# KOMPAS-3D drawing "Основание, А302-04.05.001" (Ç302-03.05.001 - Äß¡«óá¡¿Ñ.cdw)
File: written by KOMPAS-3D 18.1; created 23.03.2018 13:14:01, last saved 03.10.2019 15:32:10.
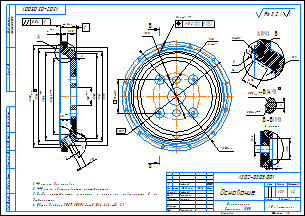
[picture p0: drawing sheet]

Sheet 1: A3, landscape

Document properties: Автор: Милов; Организация: Милов; Полное имя файла: D:\Мембранные насосы\Мембранный электропривод\А302-00.00.000 - ASTRA-302 (МЭ200)\Чертежи Полипропилен\А302-03.05.001 - Основание.cdw; Параметр неуказанной шероховатости: Ra 3,2; Масса: 1.33492

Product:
- Part/product: Основание  | designation А302-04.05.001
    Материал: Полипропилен  ГОСТ 26996-86 (density 900 kg/m3)
    Масса: 1.33492
    Раздел спецификации: Детали
    Форматы листов документа: A3
    source file: ..\Чертежи ПВХ\А302-02.05.001 - Основание.cdw, А302-03.05.001 - Основание.cdw
- Part/product: Основание  | designation А302-00.05.001
    Материал: Полипропилен  ГОСТ 26996-86 (density 900 kg/m3)
    Масса: 1.33086
    Раздел спецификации: Детали
    Форматы листов документа: A3
    source file: \\192.168.87.28\Konstructor_doc\Мембранные насосы\Мембранный электропривод\А302-00.00.000 - ASTRA-302 (МЭ200)\Чертежи\А302-00.05.001 - Основание.cdw
- Part/product: Основание  | designation А302-03.05.001
    Материал: Полипропилен  ГОСТ 26996-86 (density 900 kg/m3)
    Масса: 1.33086
    Раздел спецификации: Детали
    Форматы листов документа: A3

Title block, sheet 1: Наименование: Основание; designation: А302-03.05.001; Материал: Полипропилен / Стержень  300; Масса: 1,33; scale: 1:2; Количество листов документа: 1; organisation: АО «Астерион»; Форматы листов документа: A3; stored path: \\192.168.87.28\Konstructor_doc\Мембранные насосы\Мембранный электропривод\А302-00.00.000 - ASTRA-302 (МЭ200)\Чертежи\А302-00.05.001 - Основание.cdw; Разработал: Лифлянд; Проверил: Борисенко; Т. контр.: Лучихин; Утвердил: Григорьева

Views: Вид 1, Местный разрез 1, Вид:3, Проекционный вид 2, Выносной элемент 3, Разрез 4, Выносной элемент 5, Выносной элемент А, Выносной элемент, Разрез В-В, Выносной элемент Б
Referenced files in D:\Мембранные насосы\Мембранный электропривод\А302-00.00.000 - ASTRA-302 (МЭ200)\3Д\: А302-00.05.001 - Основание.m3d
Referenced files in Z:\Мембранные насосы\Мембранный электропривод\А302-00.00.000 - ASTRA-302 (МЭ200)\3Д\: А302-00.05.001 - Основание.m3d
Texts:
  Ra 3,2
  Ra 3,2 ( )
Dimensions and other numbers on the sheet: 16; 9; 50; 4; 44,5; 272; 28; 280; 211,67; 244; 0,04; 23,5; 247; 235; 2; 264; 300; 20; 2 отв.; 130; 287; 12 отв.; 7; 92±0,2; 6; 12; 2,5; 15; 1±0,1; 4 места; 8,5; 0,5; 1:2; 1,33; 03.10.2019

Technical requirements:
  *Размеры для справок.
  **Размер обеспечивается инструментом.
  Следы инструмента, царапины и риски на поверхности Д не
  допускаются.
  Общие допуски ГОСТ 30893.2-mK (H14, h14,  t2/2).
